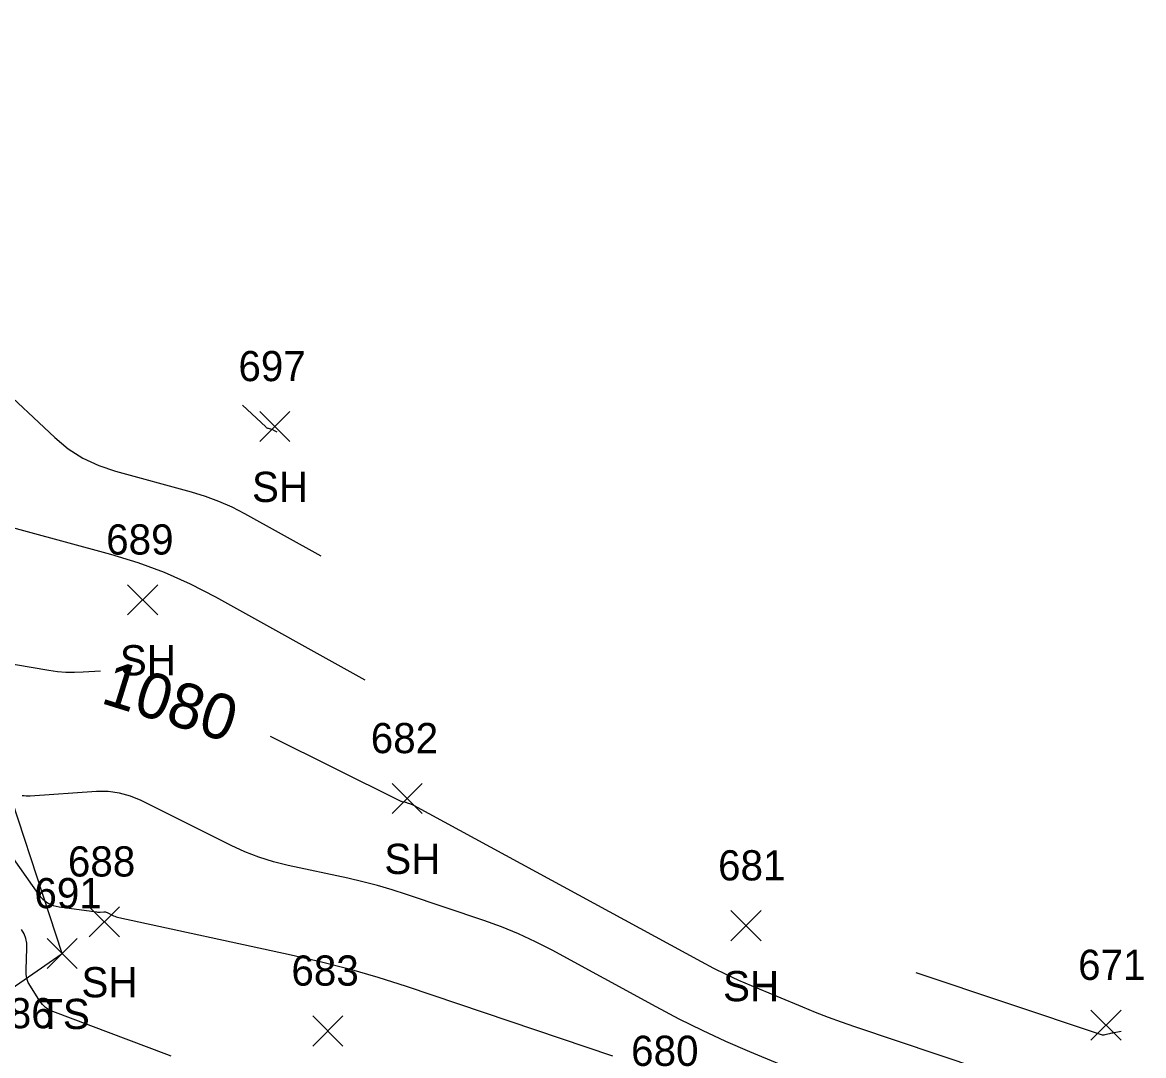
# Model space of a CAD drawing. Extents: x 1592612 to 1596497, y 111838 to 113741.
# Drawn here: x 1592925.8 to 1593000.1, y 113460.9 to 113529.3 of the extents above; entities that cross this region are included whole.
import ezdxf

# ---------------------------------------------------------------- set-up
doc = ezdxf.new("R2010")
doc.units = 0
for name, color, linetype in [('L_A', 7, 'Continuous'), ('L_I', 7, 'Continuous'), ('L_TIC', 7, 'Continuous'), ('LELB', 7, 'Continuous'), ('LSOGCMA', 7, 'Continuous'), ('LSOGCMA_T', 7, 'Continuous'), ('LSOGCMI', 7, 'Continuous')]:
    doc.layers.add(name, color=color, linetype=linetype)

msp = doc.modelspace()

# ---------------------------------------------------------------- linework, layer by layer
at = {"layer": 'L_TIC'}
for points in [[(1592941.544, 113501.567), (1592943.544, 113503.567)], [(1592943.544, 113501.567), (1592941.544, 113503.567)], [(1592932.799, 113490.085), (1592934.799, 113492.085)], [(1592934.799, 113490.085), (1592932.799, 113492.085)], [(1592950.305, 113476.933), (1592952.305, 113478.933)], [(1592952.305, 113476.933), (1592950.305, 113478.933)], [(1592930.257, 113468.765), (1592932.257, 113470.765)], [(1592932.257, 113468.765), (1592930.257, 113470.765)], [(1592972.728, 113468.506), (1592974.728, 113470.506)], [(1592974.728, 113468.506), (1592972.728, 113470.506)], [(1592927.472, 113466.665), (1592929.472, 113468.665)], [(1592929.472, 113466.665), (1592927.472, 113468.665)], [(1592996.562, 113461.918), (1592998.562, 113463.918)], [(1592998.562, 113461.918), (1592996.562, 113463.918)], [(1592945.052, 113461.538), (1592947.052, 113463.538)], [(1592947.052, 113461.538), (1592945.052, 113463.538)]]:
    msp.add_lwpolyline(points, dxfattribs=at)
at = {"layer": 'LELB'}
msp.add_lwpolyline([(1592918.957, 113461.096), (1592928.472, 113467.665), (1592923.872, 113481.628), (1592916.743, 113497.854), (1592906.203, 113506.134), (1592893.782, 113529.323)], dxfattribs=at)
at = {"layer": 'LSOGCMA'}
for points in [[(1592923.147, 113487.186), (1592927.59, 113486.431), (1592928.153, 113486.352), (1592928.716, 113486.307), (1592929.282, 113486.294), (1592929.849, 113486.315), (1592931.006, 113486.391)], [(1592942.228, 113482.068), (1592950.795, 113477.796), (1592950.835, 113477.778), (1592950.876, 113477.762), (1592950.918, 113477.749), (1592950.961, 113477.738), (1592951.134, 113477.701), (1592951.177, 113477.691), (1592951.219, 113477.68), (1592951.262, 113477.668), (1592951.304, 113477.654), (1592951.528, 113477.579), (1592951.579, 113477.56), (1592951.629, 113477.54), (1592951.677, 113477.517), (1592951.725, 113477.492), (1592970.761, 113467.129), (1592971.574, 113466.7), (1592972.396, 113466.293), (1592973.229, 113465.907), (1592974.073, 113465.543), (1592977.466, 113464.13), (1592978.318, 113463.784), (1592979.175, 113463.453), (1592980.038, 113463.138), (1592980.906, 113462.838), (1592994.768, 113458.183)]]:
    msp.add_lwpolyline(points, dxfattribs=at)
at = {"layer": 'LSOGCMI'}
for points in [[(1592948.516, 113485.775), (1592938.631, 113491.271), (1592936.963, 113492.135), (1592935.251, 113492.892), (1592933.496, 113493.544), (1592931.698, 113494.091), (1592917.634, 113497.908), (1592917.519, 113497.947), (1592917.411, 113497.999), (1592917.31, 113498.063), (1592917.216, 113498.141), (1592916.857, 113498.478), (1592916.772, 113498.566), (1592916.698, 113498.661), (1592916.635, 113498.764), (1592916.582, 113498.874), (1592911.693, 113510.666), (1592911.099, 113512.081), (1592910.49, 113513.489), (1592909.868, 113514.891), (1592909.232, 113516.287), (1592905.372, 113524.646)], [(1592911.729, 113522.081), (1592912.99, 113519.35), (1592913.198, 113518.893), (1592913.401, 113518.435), (1592913.6, 113517.975), (1592913.795, 113517.513), (1592914.92, 113514.799), (1592915.2, 113514.212), (1592915.537, 113513.664), (1592915.931, 113513.156), (1592916.382, 113512.688), (1592927.974, 113501.842), (1592928.875, 113501.094), (1592929.845, 113500.471), (1592930.886, 113499.973), (1592931.996, 113499.6), (1592937.007, 113498.24), (1592937.925, 113497.961), (1592938.821, 113497.628), (1592939.695, 113497.241), (1592940.547, 113496.8), (1592945.593, 113493.995)], [(1592940.41, 113503.973), (1592941.945, 113502.537), (1592941.982, 113502.506), (1592942.022, 113502.48), (1592942.065, 113502.46), (1592942.11, 113502.445), (1592942.317, 113502.389), (1592942.354, 113502.377), (1592942.391, 113502.363), (1592942.427, 113502.347), (1592942.462, 113502.329), (1592942.67, 113502.214)], [(1592921.596, 113479.093), (1592926.914, 113471.581), (1592927.187, 113471.263), (1592927.506, 113471.019), (1592927.869, 113470.849), (1592928.277, 113470.754), (1592930.743, 113470.417), (1592930.802, 113470.411), (1592930.862, 113470.407), (1592930.921, 113470.406), (1592930.98, 113470.409), (1592931.218, 113470.425), (1592931.277, 113470.425), (1592931.334, 113470.417), (1592931.39, 113470.402), (1592931.444, 113470.379), (1592931.863, 113470.17), (1592931.951, 113470.13), (1592932.042, 113470.095), (1592932.135, 113470.065), (1592932.229, 113470.042), (1592943.628, 113467.588), (1592945.552, 113467.146), (1592947.462, 113466.649), (1592949.356, 113466.099), (1592951.236, 113465.495), (1592964.892, 113460.894)], [(1592983.268, 113457.295), (1592973.987, 113461.16), (1592972.409, 113461.841), (1592970.85, 113462.563), (1592969.31, 113463.325), (1592967.789, 113464.128), (1592960.895, 113467.881), (1592959.799, 113468.448), (1592958.681, 113468.965), (1592957.542, 113469.433), (1592956.382, 113469.852), (1592951.27, 113471.575), (1592950.309, 113471.883), (1592949.341, 113472.165), (1592948.364, 113472.418), (1592947.381, 113472.645), (1592943.431, 113473.495), (1592942.454, 113473.737), (1592941.498, 113474.039), (1592940.562, 113474.4), (1592939.648, 113474.821), (1592933.691, 113477.792), (1592932.984, 113478.089), (1592932.257, 113478.287), (1592931.511, 113478.385), (1592930.744, 113478.384), (1592926.358, 113478.094), (1592926.221, 113478.088), (1592926.084, 113478.09), (1592925.947, 113478.098), (1592925.811, 113478.113)], [(1592935.689, 113460.874), (1592935.399, 113460.981), (1592927.844, 113463.819), (1592927.586, 113463.939), (1592927.357, 113464.096), (1592927.157, 113464.288), (1592926.986, 113464.516), (1592926.363, 113465.501), (1592926.228, 113465.753), (1592926.136, 113466.016), (1592926.085, 113466.29), (1592926.077, 113466.576), (1592926.14, 113468.025), (1592926.128, 113468.356), (1592926.064, 113468.671), (1592925.947, 113468.971), (1592925.778, 113469.255)], [(1592998.572, 113462.512), (1592998.096, 113462.413), (1592998.02, 113462.397), (1592997.945, 113462.381), (1592997.869, 113462.365), (1592997.794, 113462.348), (1592997.492, 113462.28), (1592997.417, 113462.268), (1592997.342, 113462.266), (1592997.268, 113462.275), (1592997.194, 113462.295), (1592984.99, 113466.393)]]:
    msp.add_lwpolyline(points, dxfattribs=at)

# ---------------------------------------------------------------- texts
at = {"layer": 'L_A'}
for s, p in [('SH', (1592941.033, 113497.567)), ('SH', (1592932.288, 113486.085)), ('SH', (1592949.794, 113472.933)), ('SH', (1592929.746, 113464.765)), ('SH', (1592972.216, 113464.506)), ('TS', (1592926.882, 113462.665))]:
    msp.add_text(s, height=2, dxfattribs=at).set_placement(p)
at = {"layer": 'L_I'}
for s, p in [('697', (1592940.135, 113505.567)), ('689', (1592931.382, 113494.085)), ('682', (1592948.896, 113480.933)), ('688', (1592928.848, 113472.765)), ('681', (1592971.885, 113472.506)), ('691', (1592926.63, 113470.665)), ('683', (1592943.642, 113465.538)), ('671', (1592995.719, 113465.918)), ('686', (1592923.445, 113462.718)), ('680', (1592966.131, 113460.223))]:
    msp.add_text(s, height=2, dxfattribs=at).set_placement(p)
at = {"layer": 'LSOGCMA_T'}
msp.add_text('1080', height=3, rotation=342.70762, dxfattribs=at).set_placement((1592930.941, 113484.278))

doc.saveas('drawing.dxf')
